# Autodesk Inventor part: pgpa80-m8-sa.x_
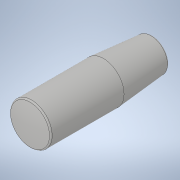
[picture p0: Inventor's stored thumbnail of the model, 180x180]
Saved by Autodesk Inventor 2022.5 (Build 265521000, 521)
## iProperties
Created: 2021-08
Part Number: pgpa80-m8-sa.x_
Material: 一般
Document SubType Name: Modeling
Designer: ImaoCorp
Density: 1 g/cm^3
Appearance: 既定
Sending System: SOLIDWORKS 2019-2019304
MC: AMD64
MC_MODEL: Intel64 Family 6 Model 60 Stepping 3, GenuineIntel
OS: Windows_NT
FRU: Parasolid Version 31.0, build 290,  9- 1-2019
FORMAT: text
GUISE: transmit
KEY: pgpa80-m8-sa
FILE: pgpa80-m8-sa.x_t
DATE: Wed Aug 11 15:02:17 2021
Author: ImaoCorp
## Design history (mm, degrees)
feature "Base1"
node "ソリッド1"
